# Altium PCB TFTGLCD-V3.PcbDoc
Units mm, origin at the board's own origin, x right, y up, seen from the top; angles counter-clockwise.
Board outline 42 x 51.5 mm, 2 copper layers (Top Layer, Bottom Layer); 24 components, 43 nets, 150 pads, 32 vias.
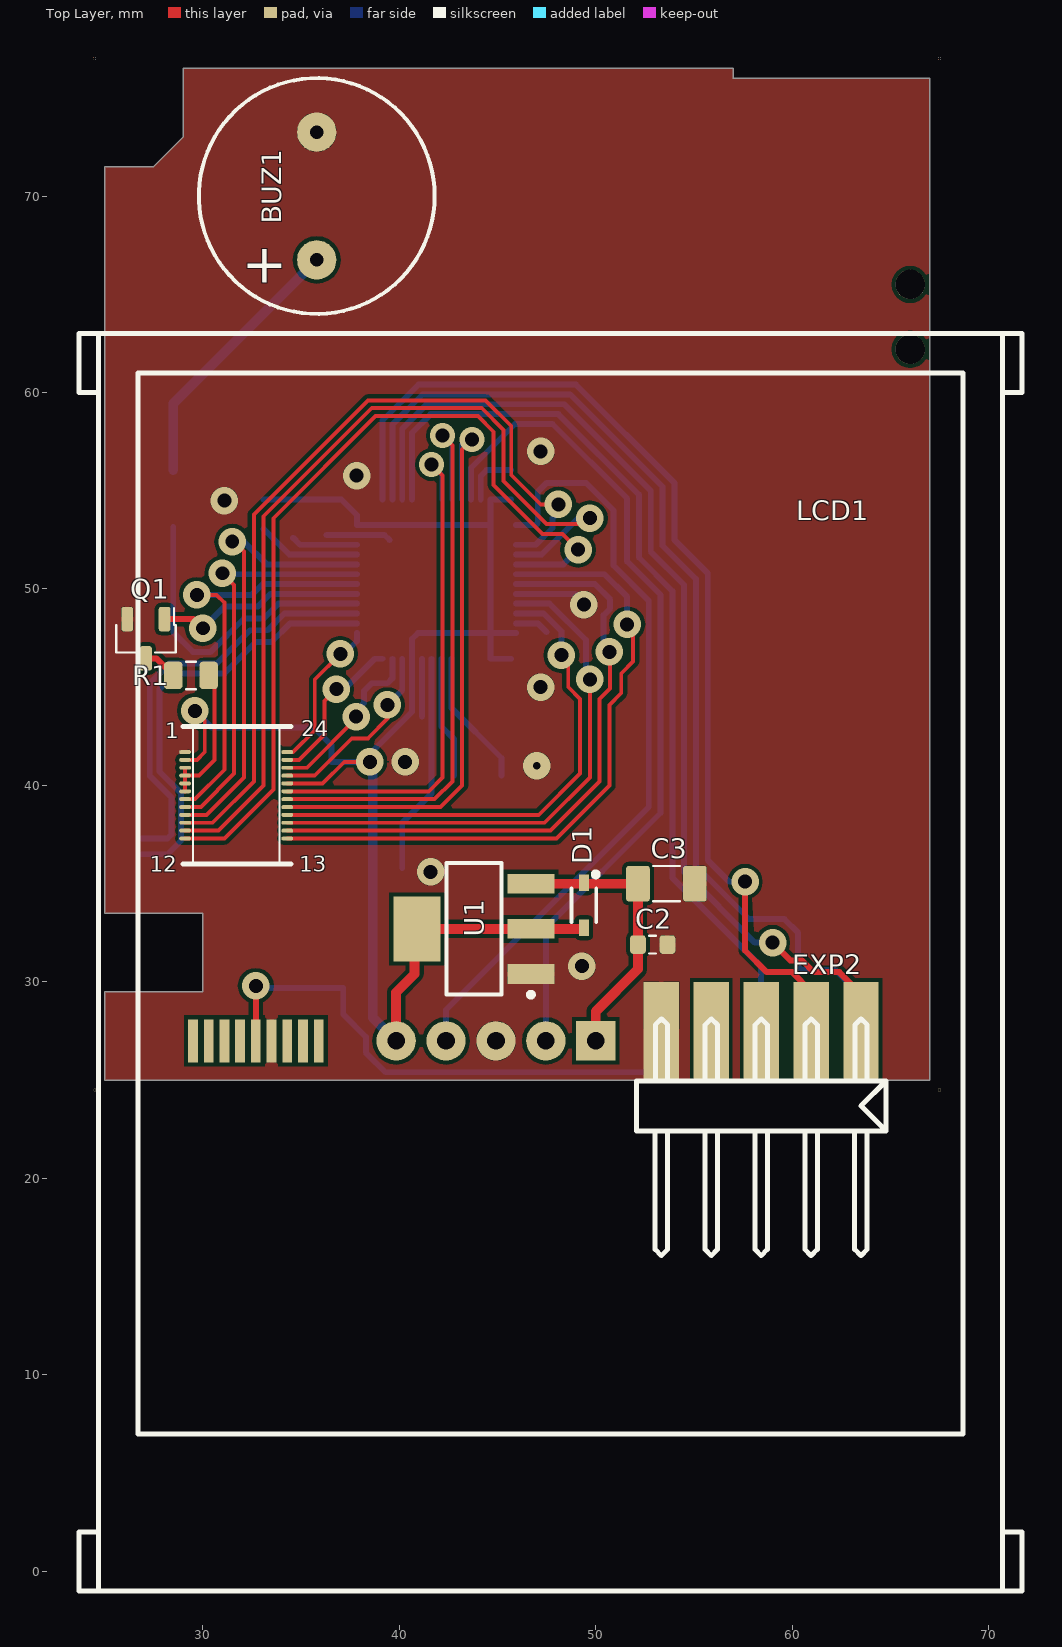
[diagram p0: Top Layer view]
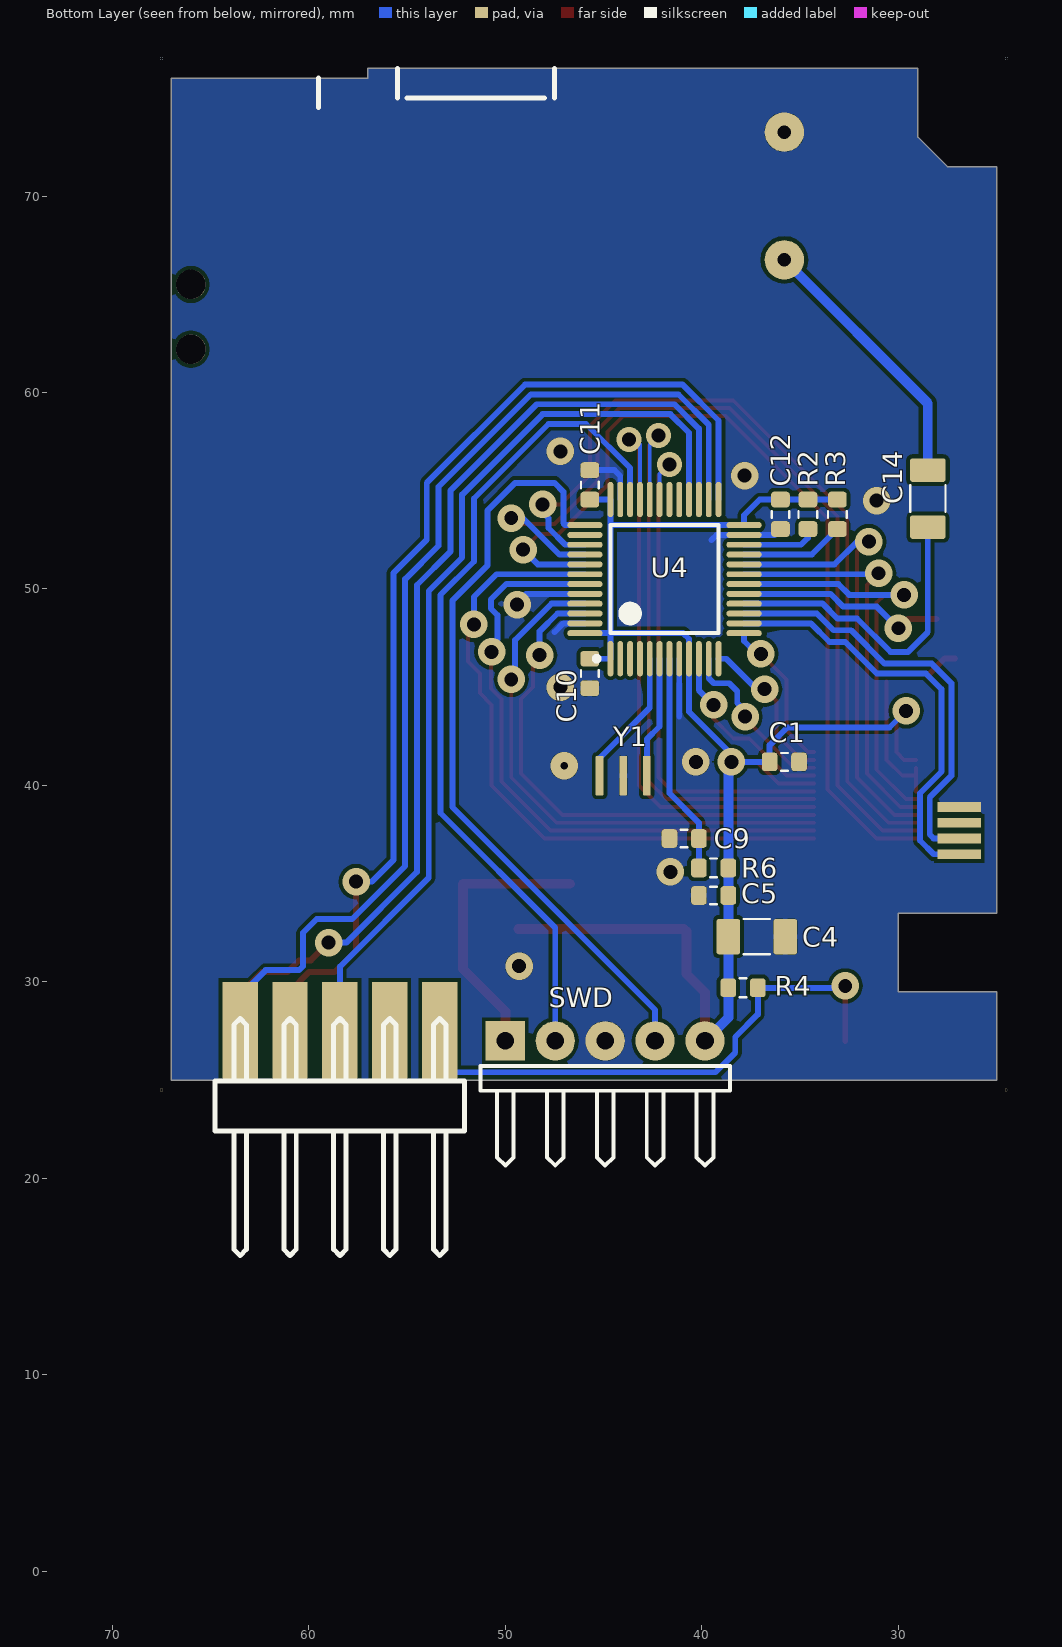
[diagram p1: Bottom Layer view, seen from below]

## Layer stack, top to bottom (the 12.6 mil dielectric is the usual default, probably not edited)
Top Layer: signal copper 0.0356
Dielectric: dielectric 0.32, FR-4, Dk 4.8
Bottom Layer: signal copper 0.0356

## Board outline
25,25 25,29.5 30,29.5 30,33.5 25,33.5 25,71.5 27.5,71.5 29,73 29,76.5 57,76.5 57,76 67,76 67,25

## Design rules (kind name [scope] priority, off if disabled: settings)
Clearance Clearance_1 [All] p1: gap=0.2
Clearance [All vs IsFill] p2: gap=0.3
ComponentClearance [All] p1 off: gap=0.254 collisioncheckmode=3 verticalgap=0.254 showdistances=FALSE
PlaneConnect [All] p1: planeconnectstyle=Relief reliefexpansion=0.508 reliefentries=4 reliefconductorwidth=0.254 reliefairgap=0
PolygonConnect [All] p1: connectstyle=Relief reliefconductorwidth=0.254 reliefentries=4 polygonreliefangle="90 Angle" airgapwidth=0
RoutingVias [All] p1: holewidth=0.711 width=1.27 viastyle="Through Hole" minholewidth=0.711 minwidth=1.27 maxholewidth=0.711 maxwidth=1.27
SilkToSilkClearance [All] p1 off: silktosilkclearance=0.254
SilkscreenOverComponentPads [IsPad] p1 off: minsilkscreentomaskgap=0.254
SolderMaskExpansion [All] p1: expansion=0.102
Width [All] p1: maxlimit=0.8 minlimit=0.2 preferedwidth=0.3
24 further rules are at their usual default settings.

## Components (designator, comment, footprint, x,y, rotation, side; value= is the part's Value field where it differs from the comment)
BUZ1 "Buzer 1205" Buzer_12xx 35.8,70 r90 top
C1 "Cap" C0603_Samsung 35.8,41.2 r0 bottom
C2 "Cap" C0603_Samsung 52.9,31.9 r180 top
C3 "Cap" C1206_Murata 53.6,35 r180 top
C4 "Cap" C1206_Murata 37.2,32.3 r0 bottom
C5 "Cap" C0603_Samsung 39.4,34.4 r180 bottom
C9 "Cap" C0603_Samsung 40.9,37.3 r180 bottom
C10 "Cap" C0603_Samsung 45.7,45.7 r90 bottom
C11 "Cap" C0603_Samsung 45.7,55.3 r270 bottom
C12 "Cap" C0603_Samsung 36,53.8 r90 bottom
C14 "Cap" C1206_Murata 28.5,54.6 r270 bottom
D1 "D_Schottky" SOD323FL_NXP 49.4,33.9 r270 top
EXP2 "BH-10" "BH-10 Slot small" 63.5,27.5 r180 top
LCD1 "ILI9325" "Mini-IPhone 24pin" 31.7,39.5 r270 top locked
Q1 "IRLML6344" SOT23-3_IR 27.109,47.466 r270 top
R1 "R" R0805_UniOhm 29.4,45.6 r180 top
R2 "R" R0603_UniOhm 34.6,53.8 r90 bottom
R3 "R" R0603_UniOhm 33.1,53.8 r90 bottom
R4 "R" R0603_UniOhm 37.9,29.7 r180 bottom
R6 "R" R0603_UniOhm 39.4,35.8 r0 bottom
SWD "Header 5H" HDR1X5H 50,27 r180 bottom
U1 "LM1117IMP-3.3" MP04A_N 43.8,32.7 r180 top
U4 "STM32F103C8T6" LQFP48_N 41.9,50.5 r90 bottom
Y1 "XTAL_CAP" CSTCE_G 44,40.5 r90 bottom

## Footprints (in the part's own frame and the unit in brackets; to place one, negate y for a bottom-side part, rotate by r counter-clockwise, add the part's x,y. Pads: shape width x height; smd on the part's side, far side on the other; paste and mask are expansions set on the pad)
"BH-10 Slot small" [mm]
  rect 1.8x5 smd: 1(0,0) 3(2.54,0) 5(5.08,0) 7(7.62,0) 9(10.16,0)
  rect 1.8x5 smd far side: 2(0,0) 4(2.54,0) 6(5.08,0) 8(7.62,0) 10(10.16,0)
  silkscreen extent -1.27,-0.62 11.43,11.43, body extent -1.25,-0.6 11.45,11.4, height 1.6
Buzer_12xx [mm]
  round 2 hole 0.7: 1(-3.25,0) 2(3.25,0)
  silkscreen extent -6,-6 6,6, body extent -5.95,-5.99 6,5.99, height 9.5
C0603_Samsung [mm] "Capacitor, Chip; 1.60 mm L X 0.80 mm W X 0.90 mm H body"
  rrect40% 0.8x0.95 smd paste-0.025 mask+0.05: 1(-0.75,0) 2(0.75,0)
  silkscreen extent -0.17,-0.45 0.17,0.45, body extent -0.8,-0.4 0.8,0.4, height 0.9
C1206_Murata [mm] "Capacitor, Chip; 3.20 mm L X 1.60 mm W X 1.80 mm H body"
  rrect20% 1.2x1.8 smd: 1(-1.45,0) 2(1.45,0)
  silkscreen extent -0.67,-0.9 0.67,0.9, body extent -1.6,-0.9 1.6,0.9, height 1.6
CSTCE_G [mm]
  rrect15% 2x0.4 smd paste-0.025 mask+0.05: 1(0,1.2) 2(0,0) 3(0,-1.2)
  body extent -0.65,-1.6 0.65,1.6, height 0.7
HDR1X5H [mm] "Connector; Header; 5 Position; Right Angle"
  rect 2x2 hole 0.9: 1(0,0)
  round 2 hole 0.9: 2(2.54,0) 3(5.08,0) 4(7.62,0) 5(10.16,0)
  silkscreen extent -1.27,-6.35 11.43,-1.27
LQFP48_N [mm] "Thin QFP, 48-Leads, Body 7x7mm, Pitch 0.5mm, IPC Medium Density"
  oval 1.8x0.3 smd: 1(-4.05,2.75) 2(-4.05,2.25) 3(-4.05,1.75) 4(-4.05,1.25) 5(-4.05,0.75) 6(-4.05,0.25) 7(-4.05,-0.25) 8(-4.05,-0.75) 9(-4.05,-1.25) 10(-4.05,-1.75) 11(-4.05,-2.25) 12(-4.05,-2.75) 25(4.05,-2.75) 26(4.05,-2.25) 27(4.05,-1.75) 28(4.05,-1.25) 29(4.05,-0.75) 30(4.05,-0.25) 31(4.05,0.25) 32(4.05,0.75) 33(4.05,1.25) 34(4.05,1.75) 35(4.05,2.25) 36(4.05,2.75)
  oval 0.3x1.8 smd: 13(-2.75,-4.05) 14(-2.25,-4.05) 15(-1.75,-4.05) 16(-1.25,-4.05) 17(-0.75,-4.05) 18(-0.25,-4.05) 19(0.25,-4.05) 20(0.75,-4.05) 21(1.25,-4.05) 22(1.75,-4.05) 23(2.25,-4.05) 24(2.75,-4.05) 37(2.75,4.05) 38(2.25,4.05) 39(1.75,4.05) 40(1.25,4.05) 41(0.75,4.05) 42(0.25,4.05) 43(-0.25,4.05) 44(-0.75,4.05) 45(-1.25,4.05) 46(-1.75,4.05) 47(-2.25,4.05) 48(-2.75,4.05)
  silkscreen extent -4.17,-2.75 2.75,3.58, body extent -3.5,-3.5 3.5,3.5, height 1.6
"Mini-IPhone 24pin" [mm]
  oval 0.2x0.6 smd: 1(-2.2,-2.6) 2(-1.8,-2.6) 3(-1.4,-2.6) 4(-1,-2.6) 5(-0.6,-2.6) 6(-0.2,-2.6) 7(0.2,-2.6) 8(0.6,-2.6) 9(1,-2.6) 10(1.4,-2.6) 11(1.8,-2.6) 12(2.2,-2.6) 13(2.2,2.6) 14(1.8,2.6) 15(1.4,2.6) 16(1,2.6) 17(0.6,2.6) 18(0.2,2.6) 19(-0.2,2.6) 20(-0.6,2.6) 21(-1,2.6) 22(-1.4,2.6) 23(-1.8,2.6) 24(-2.2,2.6)
  silkscreen extent -23.5,-8 40.5,40, body extent -23.5,-8 40.6,40, height 4.2
MP04A_N [mm] "SOT223, 4-Leads, Body 6.5x3.5mm, Pitch 2.3mm, Lead Span 7mm, IPC Medium Density"
  rect 2.4x1 smd: 1(-2.9,2.3) 2(-2.9,0) 3(-2.9,-2.3)
  rect 2.4x3.3 smd: 4(2.9,0)
  silkscreen extent -3.03,-3.35 1.4,3.47, body extent -1.85,-3.35 1.85,3.35, height 1.8
R0603_UniOhm [mm] "Resistor, Chip; 1.60 mm L X 0.825 mm W X 0.55 mm H body"
  rrect40% 0.8x0.95 smd paste-0.025 mask+0.05: 1(-0.75,0) 2(0.75,0)
  silkscreen extent -0.17,-0.48 0.17,0.48, body extent -0.8,-0.41 0.8,0.41, height 0.55
R0805_UniOhm [mm] "Resistor, Chip; 2.00 mm L X 1.275 mm W X 0.65 mm H body"
  rrect40% 0.95x1.4 smd paste-0.025 mask+0.05: 1(-0.9,0) 2(0.9,0)
  silkscreen extent -0.25,-0.7 0.25,0.7, body extent -1,-0.64 1,0.64, height 0.65
SOD323FL_NXP [mm] "SODFL Diode;1.80mm W X 1.35mm L X 0.80mm H body"
  rrect10% 0.85x0.5 smd paste-0.025 mask+0.05: A(1.14,0) C(-1.14,0)
  silkscreen extent -1.7,-0.63 0.85,0.73, body extent -1.35,-0.67 1.35,0.68, height 0.79
SOT23-3_IR [mm] "Small Outline Transistor (SOT23), 0.95 mm pitch; 3 pin, 2.92 mm L X 1.30 mm W X 1.12 mm H body"
  rrect40% 1.25x0.6 smd paste-0.025 mask+0.05: 1(-1,0.95) 2(-1,-0.95) 3(1,0)
  silkscreen extent -1.57,-1.52 0.7,1.52, body extent -1.18,-1.46 1.18,1.46, height 1.12

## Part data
BUZ1: library part Buzer
C1 C2 C5 C9 C10 C11 C12: library part CL10B104KB8NNNC
C3 C4 C14: library part GRM31CR71H475KA12L
D1: library part PMEG2020EJ,115, "20V, 2A very low VF MEGA Schottky barrier rectifiers"
EXP2: library part "BH-10 Slot"
LCD1: library part Mini-IPhone-24pin
Q1: library part IRLML6344TRPBF, "30 V, 5.0 A, 0.029 Ohm Single N-Channel HEXFET Power MOSFET"
R1: library part 0805S8F4700T50
R2 R3 R4 R6: library part 0603SAF1002T50
SWD: "Header, 5-Pin, Right Angle"
U1: "800mA Low-Dropout Linear Regulator"
U4: "STM32 ARM-based 32-bit MCU with 64 Kbytes Flash, 48-pin LQFP, Industrial Temperature"
Y1: library part CSTCE10M0G55Z-R0, "SMD 10 MHz 0.5%, 0.2%(TC) Build in Load Capacitance 33pF ± 20%"

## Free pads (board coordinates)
  round 0.15 hole 0.15: 0(24.5,24.5) 0(24.5,77) 0(67.5,24.5) 0(67.5,77)
  round 1.5 hole 1.5: 0(66,62.2) 0(66,65.5)
  rect 0.5x2.2 smd: 1(29.5,27) 2(30.3,27) 3(31.1,27) 4(31.9,27) 5(32.7,27) 6(33.5,27) 7(34.3,27) 8(35.1,27) 9(35.9,27)
  rect 2.2x0.5 smd far side: 10(26.9,36.5) 11(26.9,37.3) 12(26.9,38.1) 13(26.9,38.9)

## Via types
v1: diameter 1.4, hole 0.711, Top Layer to Bottom Layer, 27 vias
v2: diameter 1.27, hole 0.711, Top Layer to Bottom Layer, 3 vias
v3: diameter 1.4, hole 0.7, Top Layer to Bottom Layer, 1 vias
v4: diameter 1.4, hole 0.4, Top Layer to Bottom Layer, 1 vias

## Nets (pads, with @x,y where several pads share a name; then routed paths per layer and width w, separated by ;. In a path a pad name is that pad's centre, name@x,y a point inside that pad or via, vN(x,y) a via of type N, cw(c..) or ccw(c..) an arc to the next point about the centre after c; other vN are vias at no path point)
+3.3V: C1.2 C4.2 C5.2 C10.2 C11.2 C12.2 D1.A LCD1.2 LCD1.20 R2.2 R3.2 R4.1 R6.1 SWD.5 U1.2 U1.4 U4.1 U4.9 U4.24 U4.36 U4.48 | length 82.8
  Top Layer w0.2: LCD1.2 29.7,41.3 30.1,41.7 30.1,43.3 v1(29.6,43.8) ; LCD1.20 36.1,40.1 37.2,41.2 v1(38.5,41.2)
  Top Layer w0.5: SWD.5 39.84,29.465 40.78,30.405 40.78,32.58 U1.4 U1.2 D1.A@49.34,32.7
  Bottom Layer w0.2: v1@38.45,41.25 v1@38.45,41.55
  Bottom Layer w0.3: v1(29.6,43.8) 30.45,42.95 35.65,42.95 36.55,42.05 C1.2 v1(38.5,41.2) ; R3.2 R2.2 C12.2 37.05,54.55 37.85,53.75 U4.24 44.6,53.25 ; v1@38.45,41.55 40.65,43.75 U4.9 40.65,47.45 40.95,47.75 44.65,47.75 ; C10.2 U4.1 44.65,47.75 ; C11.2 U4.36 44.65,47.75 ; U4.48 44.65,47.75
  Bottom Layer w0.5: v1@38.65,41.05 R6.1 C5.2 C4.2 38.65,28.19 SWD.5
+5V: C2.2 C3.2 D1.C SWD.1 U1.3 | length 14.3
  Top Layer w0.5: U1.3 C3.2@52.1,35 ; SWD.1 50,28.5 52.15,30.65 C3.2
B1: pad.10 U4.14 | length 21.9
  Bottom Layer w0.3: pad.10 28.2,36.5 28.9,37.2 28.9,39.6 27.8,40.7 27.8,44.9 28.6,45.7 31.1,45.7 32.7,47.3 33.5,47.3 34.45,48.25 U4.14
B2: pad.11 U4.15 | length 21.8
  Bottom Layer w0.3: pad.11 28.2,37.3 28.4,37.5 28.4,39.393 27.3,40.493 27.3,45.2 28.3,46.2 30.7,46.2 32.4,47.9 33.3,47.9 34.15,48.75 U4.15
B3: U4.29
B4: U4.30
BEEP: C14.2 U4.16 | length 16.1
  Bottom Layer w0.3: C14.2 28.5,47.8 29.5,46.8 30.4,46.8 32.1,48.5 33.1,48.5 33.85,49.25 U4.16
BRIGHTNES: Q1.1 U4.17 | length 10.7
  Top Layer w0.3: Q1.1 29.534,48.466 v1(30,48)
  Bottom Layer w0.3: v1(30,48) 31.1,49.1 32.8,49.1 33.45,49.75 U4.17
CS-: LCD1.18 U4.32 | length 30
  Top Layer w0.2: LCD1.18 41.8,39.3 42.7,40.2 42.7,57.3 v2(42.2,57.8)
  Bottom Layer w0.2: v2(42.2,57.8) 42.65,57.35 U4.32
D0: LCD1.7 U4.18 | length 21.1
  Top Layer w0.2: LCD1.7 29.6,39.3 31.1,40.8 31.1,49.3 30.7,49.7 v1(29.7,49.7)
  Bottom Layer w0.3: v1(29.7,49.7) 32.5,49.7 33.05,50.25 U4.18
D1: LCD1.8 U4.19 | length 20.5
  Top Layer w0.2: LCD1.8 29.9,38.9 31.6,40.6 31.6,50.2 v1(31,50.8)
  Bottom Layer w0.3: v1(31,50.8) 31.05,50.75 U4.19
D2: LCD1.9 U4.20 | length 22.8
  Top Layer w0.2: LCD1.9 30.2,38.5 32.1,40.4 32.1,51.9 31.9,52.1 v1@31.5,52.1
  Bottom Layer w0.3: v1(31.5,52.408) 32.092,52.408 33.25,51.25 U4.20
D3: LCD1.10 U4.39 | length 43
  Top Layer w0.2: LCD1.10 30.5,38.1 32.6,40.2 32.6,53.8 38.4,59.6 44.4,59.6 45.7,58.3 45.7,55.8 47.2,54.3 v1(48.1,54.3)
  Bottom Layer w0.3: U4.39 46.95,52.25 47.8,53.1 47.8,53.6 48.1,53.9 v1@48.1,54.2
D4: LCD1.11 U4.40 | length 46.1
  Top Layer w0.2: LCD1.11 30.8,37.7 33.1,40 33.1,53.7 38.6,59.2 44.2,59.2 45.3,58.1 45.3,55.5 47.5,53.3 49.4,53.3 v1(49.7,53.6)
  Bottom Layer w0.3: U4.40 47.25,51.75 49.1,53.6 v1(49.7,53.6)
D5: LCD1.12 U4.41 | length 44.8
  Top Layer w0.2: LCD1.12 31.1,37.3 33.6,39.8 33.6,53.6 38.8,58.8 44,58.8 44.8,58 44.8,55.3 47.3,52.8 48.3,52.8 v1(49.1,52)
  Bottom Layer w0.3: U4.41 48.35,51.25 v1(49.1,52)
D6: LCD1.13 U4.42 | length 33.9
  Top Layer w0.2: LCD1.13 48,37.3 50.7,40 50.7,44.1 51.3,44.7 51.3,45.7 51.9,46.3 51.9,47.9 v1(51.6,48.2)
  Bottom Layer w0.3: U4.42 50.45,50.75 51.6,49.6 v1(51.6,48.2)
D7: LCD1.14 U4.43 | length 32.4
  Top Layer w0.2: LCD1.14 47.7,37.7 50.2,40.2 50.2,44.4 50.731,44.931 50.731,47.092 50.7,47.061 v1(50.7,46.8)
  Bottom Layer w0.3: U4.43 49.95,50.25 50.731,49.469 50.731,48.997 50.4,48.666 50.4,47.423 50.731,47.092 50.7,47.061 v1(50.7,46.8)
GND: BUZ1.2 C1.1 C2.1 C3.1 C4.1 C5.1 C9.1 C10.1 C11.1 C12.1 EXP2.9 LCD1.1 pad.6 pad.13 Q1.2 SWD.3 U1.1 U4.8 U4.23 U4.35 U4.44 U4.47 Y1.2 | length 14.6
  Bottom Layer w0.3: C12.1@36.3,52.75 U4.23 39.25,52.75 39.5,52.5 ; 41.15,43.5 U4.8 ; U4.35 44.15,55.75 44.45,56.05 C11.1 ; U4.47 47.05,48.25 47.5,47.8 ; U4.44 48.95,49.75 49.4,49.3 v1(49.4,49.2)
  other v1: 49.3,30.8 41.6,35.6 40.3,41.2 47.2,45 31.1,54.5 47.2,57
  other v3: 37.827,55.773
  other v4: 47,41
KILL: EXP2.10 pad.5 R4.2 | length 26
  Top Layer w0.3: pad.5 v1(32.7,29.8)
  Bottom Layer w0.3: v1@32.7,29.7 R4.2 37.15,28.35 38.3,27.2 38.3,26.4 39.3,25.4 EXP2.10@52.9,25.4
LCD-CS: EXP2.3 U4.25 | length 53.7
  Top Layer w0.3: v1(57.6,35.1) 57.6,31.6 58.7,30.5 60,30.5 60.96,29.54 EXP2.3
  Bottom Layer w0.3: U4.25 39.15,58.571 40.979,60.4 49,60.4 54,55.4 54,52.5 55.7,50.8 55.7,36.2 56.8,35.1 v1(57.6,35.1)
MISO: EXP2.1 U4.27 | length 52.2
  Top Layer w0.3: v1(59,32) 59.9,31.1 60.5,31.1 61.1,30.5 62.4,30.5 63.5,29.4 EXP2.1
  Bottom Layer w0.3: U4.27 40.15,58.157 41.393,59.4 48.4,59.4 52.8,55 52.8,51.9 54.5,50.2 54.5,35.6 58.1,32 v1(59,32)
MOSI: EXP2.6 U4.28 | length 46.9
  Bottom Layer w0.3: U4.28 40.65,57.95 41.6,58.9 48.1,58.9 52.2,54.8 52.2,51.6 53.9,49.9 53.9,35.3 58.42,30.78 EXP2.6
NetBUZ1_1: BUZ1.1 C14.1 | length 13.7
  Bottom Layer w0.5: C14.1 28.5,59.45 BUZ1.1
NetC9_2: C9.2 R6.2 U4.7 | length 11.3
  Bottom Layer w0.3: R6.2 40.15,38.1 41.65,39.6 U4.7
NetLCD1_3: LCD1.3 LCD1.4 LCD1.5 LCD1.6 R1.1 | length 7
  Top Layer w0.2: LCD1.6 LCD1.5 LCD1.4 ; LCD1.3 LCD1.4 ; R1.1@30.6,45.3 30.6,41.3 29.8,40.5 LCD1.4
NetQ1_3: Q1.3 R1.2 | length 1.7
  Top Layer w0.3: Q1.3 27.634,46.466 R1.2
NetSWD_2: SWD.2 U4.34 | length 42.8
  Bottom Layer w0.3: U4.34 43.65,56.157 45.893,58.4 47.8,58.4 51.6,54.6 51.6,51.4 53.3,49.7 53.3,38.6 47.46,32.76 SWD.2
NetSWD_4: SWD.4 U4.37 | length 39.4
  Bottom Layer w0.3: SWD.4 42.38,28.58 52.7,38.9 52.7,49.4 50.9,51.2 50.9,54 49.5,55.4 47.5,55.4 47.05,54.95 47.05,53.35 46.95,53.25 U4.37
NetU4_5: U4.5 Y1.1 | length 7
  Bottom Layer w0.3: U4.5 42.65,43.95 45.2,41.4 Y1.1
NetU4_6: U4.6 Y1.3 | length 6.2
  Bottom Layer w0.3: U4.6 42.15,43 42.8,42.35 Y1.3
RD-: LCD1.16 U4.46 | length 26
  Top Layer w0.2: LCD1.16 47.1,38.5 49.2,40.6 49.2,44.4 48.6,45 48.6,46.28 v1(48.253,46.627)
  Bottom Layer w0.3: U4.46 47.35,48.75 48.253,47.847 v1@48.253,46.742
RS-: LCD1.19 U4.31 | length 26.4
  Top Layer w0.2: LCD1.19 41.5,39.7 42.2,40.4 42.2,55.765 v2(41.635,56.33)
  Bottom Layer w0.2: v2(41.635,56.33) 41.635,56.365 42.15,55.85 U4.31
RST-: LCD1.17 U4.33 | length 30.6
  Top Layer w0.2: LCD1.17 42.1,38.9 43.2,40 43.2,57.1 v2(43.7,57.6)
  Bottom Layer w0.2: U4.33 43.15,57.35 43.4,57.6 v2(43.7,57.6)
SCK: EXP2.2 U4.26 | length 54.1
  Bottom Layer w0.3: U4.26 39.65,58.364 41.186,59.9 48.7,59.9 53.4,55.2 53.4,52.2 55.1,50.5 55.1,35.9 57.8,33.2 59.6,33.2 60.3,32.5 60.3,30.8 60.5,30.6 62.2,30.6 63.5,29.3 EXP2.2
SCL: R3.1 U4.21 | length 5.3
  Bottom Layer w0.3: R3.1 34.4,51.75 U4.21
SD-CS: EXP2.4
SD-DET: EXP2.7
SDA: R2.1 U4.22 | length 3.4
  Bottom Layer w0.3: 34.6,52.6 34.95,52.25 U4.22
WR-: LCD1.15 U4.45 | length 27.8
  Top Layer w0.2: LCD1.15 47.4,38.1 49.7,40.4 v1(49.7,45.4)
  Bottom Layer w0.3: U4.45 47.65,49.25 49.5,47.4 49.5,45.5 49.535,45.465 v1@49.754,45.465
XL: LCD1.23 U4.12 | length 8
  Top Layer w0.2: LCD1.23 34.9,41.3 36.2,42.6 36.2,44.3 v1(36.8,44.9)
  Bottom Layer w0.3: v1(36.8,44.9) 37.2,44.9 38.75,46.45 U4.12
XR: LCD1.21 U4.10 | length 9.7
  Top Layer w0.2: LCD1.21 35.7,40.5 37.6,42.4 38.4,42.4 39.4,43.4 v1(39.4,44.1)
  Bottom Layer w0.3: v1(39.4,44.1) 40.15,44.85 U4.10
YD: LCD1.24 U4.13 | length 7.9
  Top Layer w0.2: LCD1.24 34.6,41.7 35.7,42.8 35.7,45.4 v1(37,46.7) v1@37.3,46.7
  Bottom Layer w0.3: v1@37.3,46.7 37.3,46.8 37.85,47.35 U4.13
YU: LCD1.22 U4.11 | length 9
  Top Layer w0.2: LCD1.22 35.3,40.9 37.883,43.483 37.817,43.483 v1(37.8,43.5)
  Bottom Layer w0.3: v1(37.8,43.5) v1@37.9,43.5 ; v1@37.9,43.5 37.9,43.9 38.2,44.2 38.2,44.8 38.6,45.2 39.4,45.2 39.65,45.45 U4.11
pads on no net: EXP2.5 EXP2.8 U4.2 U4.3 U4.4 U4.38

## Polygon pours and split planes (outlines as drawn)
GND on Bottom Layer "Bottom Layer-No Net" (solid, remove dead copper, pour order 4): 25,25 25,29.5 30,29.5 30,33.5 25,33.5 25,71.5 27.5,71.5 29,73 29,76.5 57,76.5 57,76 67,76 67,25
GND on Top Layer "Bottom Layer-No Net" (solid, remove dead copper, pour order 6): 25,25 25,29.5 30,29.5 30,33.5 25,33.5 25,71.5 27.5,71.5 29,73 29,76.5 57,76.5 57,76 67,76 67,25

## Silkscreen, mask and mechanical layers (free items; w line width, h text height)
Top Overlay:
  lines w0.254: 29,36 34.5,36 ; 29,43 34.5,43
Bottom Overlay:
  lines w0.254: 47.5,75 47.5,76.5 ; 48,75 55,75 ; 55.5,75 55.5,76.5 ; 59.5,74.5 59.5,76
Top Solder:
  rectangle: 57,76 67.1,76.5
  rectangle: 24.9,29.5 30,33.5
  region: 24.9,76.5 29,76.5 29,73 27.5,71.5 24.9,71.5
Bottom Solder:
  rectangle: 25,24.5 67,25
  rectangle: 24.9,76.5 67,77
  rectangle: 57,76 67.1,77
  rectangle: 24.9,29.5 30,33.5
  region: 24.9,76.5 29,76.5 29,73 27.5,71.5 24.9,71.5
Out Board:
  the board outline again, w0.254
